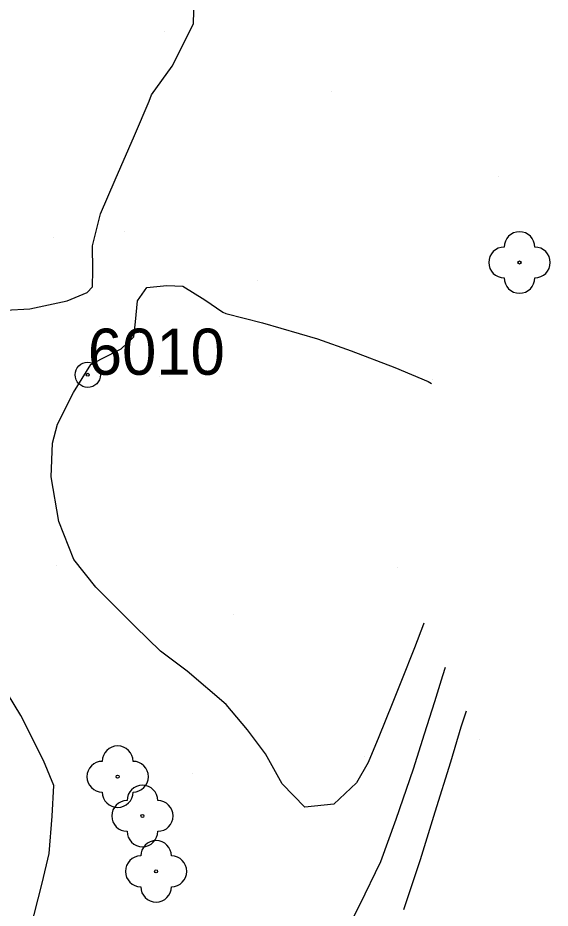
# Model space of a CAD drawing. Extents: x -448957 to -448612, y -1107690 to -1107245.
# Drawn here: x -448645.33 to -448627.99, y -1107436.62 to -1107407.65 of the extents above; entities that cross this region are included whole.
import ezdxf

# ---------------------------------------------------------------- set-up
doc = ezdxf.new("R2010")
doc.units = 0
for name, color, linetype in [('22', 7, 'Continuous'), ('63', 7, 'Continuous'), ('Default', 7, 'Continuous'), ('Vrstva 14', 7, 'Continuous'), ('Vrstva 17', 7, 'Continuous'), ('Vrstva 22', 7, 'Continuous'), ('Vrstva 63', 7, 'Continuous')]:
    doc.layers.add(name, color=color, linetype=linetype)

# ---------------------------------------------------------------- blocks, each defined once
blk = doc.blocks.new('POINT_DISPLAY')
at = {"layer": 'Default'}
blk.add_line((0, 0), (0, 0), dxfattribs=at)
blk = doc.blocks.new('STROM$5')
at = {"layer": '22'}
blk.add_circle((0, 0), 0.5, dxfattribs=at)
for centre, start, end in [((0, 5), 0, 180), ((-5, 0), 90, 270), ((5, 0), 270, 90), ((0, -5), 180, 0)]:
    blk.add_arc(centre, 5, start, end, dxfattribs=at)
blk = doc.blocks.new('PPBP$7')
at = {"layer": '63'}
for radius in [4.12, 0.5]:
    blk.add_circle((0, 0), radius, dxfattribs=at)

msp = doc.modelspace()

# ---------------------------------------------------------------- linework, layer by layer
at = {"layer": 'Vrstva 17'}
for points in [[(-448648.112, -1107413.706), (-448648.319, -1107414.386), (-448648.407, -1107414.736), (-448648.475, -1107415.011), (-448648.221, -1107415.331), (-448647.832, -1107415.765), (-448647.296, -1107416.165), (-448646.849, -1107416.487), (-448646.282, -1107416.835), (-448645.726, -1107417.167), (-448644.938, -1107417.119), (-448643.721, -1107416.865), (-448643.075, -1107416.586), (-448642.893, -1107416.401), (-448642.886, -1107415.868), (-448642.898, -1107415.067), (-448642.637, -1107414.031), (-448642.157, -1107412.92), (-448641.524, -1107411.48), (-448641.05, -1107410.369), (-448640.972, -1107410.154), (-448640.297, -1107409.225), (-448639.611, -1107407.851), (-448639.576, -1107406.556)], [(-448632.106, -1107427.344), (-448632.115, -1107427.38), (-448632.414, -1107428.155), (-448632.833, -1107429.217), (-448633.139, -1107429.976), (-448633.577, -1107431.041), (-448633.919, -1107431.877), (-448634.303, -1107432.539), (-448635.043, -1107433.24), (-448635.981, -1107433.335), (-448636.724, -1107432.58), (-448637.266, -1107431.598), (-448637.849, -1107430.816), (-448638.545, -1107429.991), (-448639.815, -1107428.915), (-448640.679, -1107428.258), (-448641.502, -1107427.457), (-448642.793, -1107426.177), (-448643.501, -1107425.272), (-448643.992, -1107424.042), (-448644.239, -1107422.588), (-448644.2, -1107421.491), (-448644.041, -1107420.869), (-448643.511, -1107419.843), (-448642.949, -1107418.933), (-448642.578, -1107418.733), (-448641.958, -1107418.422), (-448641.548, -1107418.027), (-448641.499, -1107417.549), (-448641.435, -1107416.864), (-448641.124, -1107416.427), (-448640.48, -1107416.357), (-448639.95, -1107416.379), (-448639.236, -1107416.833), (-448638.649, -1107417.228), (-448638.553, -1107417.27), (-448637.364, -1107417.573), (-448635.57, -1107418.1), (-448634.471, -1107418.49), (-448633.047, -1107419.035), (-448631.966, -1107419.489), (-448631.861, -1107419.547)], [(-448631.415, -1107428.786), (-448631.5, -1107429.061), (-448631.763, -1107429.911), (-448632.093, -1107430.961), (-448632.455, -1107432.097), (-448633.024, -1107433.731), (-448633.523, -1107435.109), (-448634.2, -1107436.522), (-448634.811, -1107437.725)], [(-448644.923, -1107437.339), (-448644.531, -1107435.812), (-448644.309, -1107434.84), (-448644.211, -1107433.623), (-448644.157, -1107432.627), (-448644.496, -1107431.811), (-448645.235, -1107430.353), (-448645.666, -1107429.635)], [(-448630.733, -1107430.209), (-448630.897, -1107430.734), (-448631.242, -1107431.868), (-448631.747, -1107433.492), (-448632.229, -1107435.045), (-448632.768, -1107436.674)]]:
    msp.add_lwpolyline(points, dxfattribs=at)

# ---------------------------------------------------------------- block references
at = {"layer": 'Vrstva 14', "xscale": 0.1, "yscale": 0.10000000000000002}
for p in [(-448640.545, -1107408.084), (-448635.121, -1107410.057), (-448629.683, -1107412.808), (-448641.844, -1107414.619), (-448644.178, -1107414.81), (-448637.511, -1107416.192), (-448640.726, -1107419.337), (-448631.84, -1107419.433), (-448644.081, -1107425.469), (-448632.971, -1107425.54), (-448638.302, -1107427.079), (-448630.285, -1107431.144), (-448634.04, -1107431.701), (-448639.649, -1107432.226), (-448644.112, -1107432.62)]:
    msp.add_blockref('POINT_DISPLAY', p, dxfattribs=at)
at = {"layer": 'Vrstva 22', "xscale": 0.1, "yscale": 0.10000000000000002}
for p in [(-448628.992, -1107415.613), (-448642.077, -1107432.344), (-448641.27, -1107433.62), (-448640.825, -1107435.423)]:
    msp.add_blockref('STROM$5', p, dxfattribs=at)
at = {"layer": 'Vrstva 63', "xscale": 0.1, "yscale": 0.10000000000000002}
msp.add_blockref('PPBP$7', (-448643.05, -1107419.266), dxfattribs=at)

# ---------------------------------------------------------------- texts
at = {"layer": 'Vrstva 63'}
msp.add_text('6010', height=1.5, dxfattribs=at).set_placement((-448643.05, -1107419.266))

doc.saveas('drawing.dxf')
